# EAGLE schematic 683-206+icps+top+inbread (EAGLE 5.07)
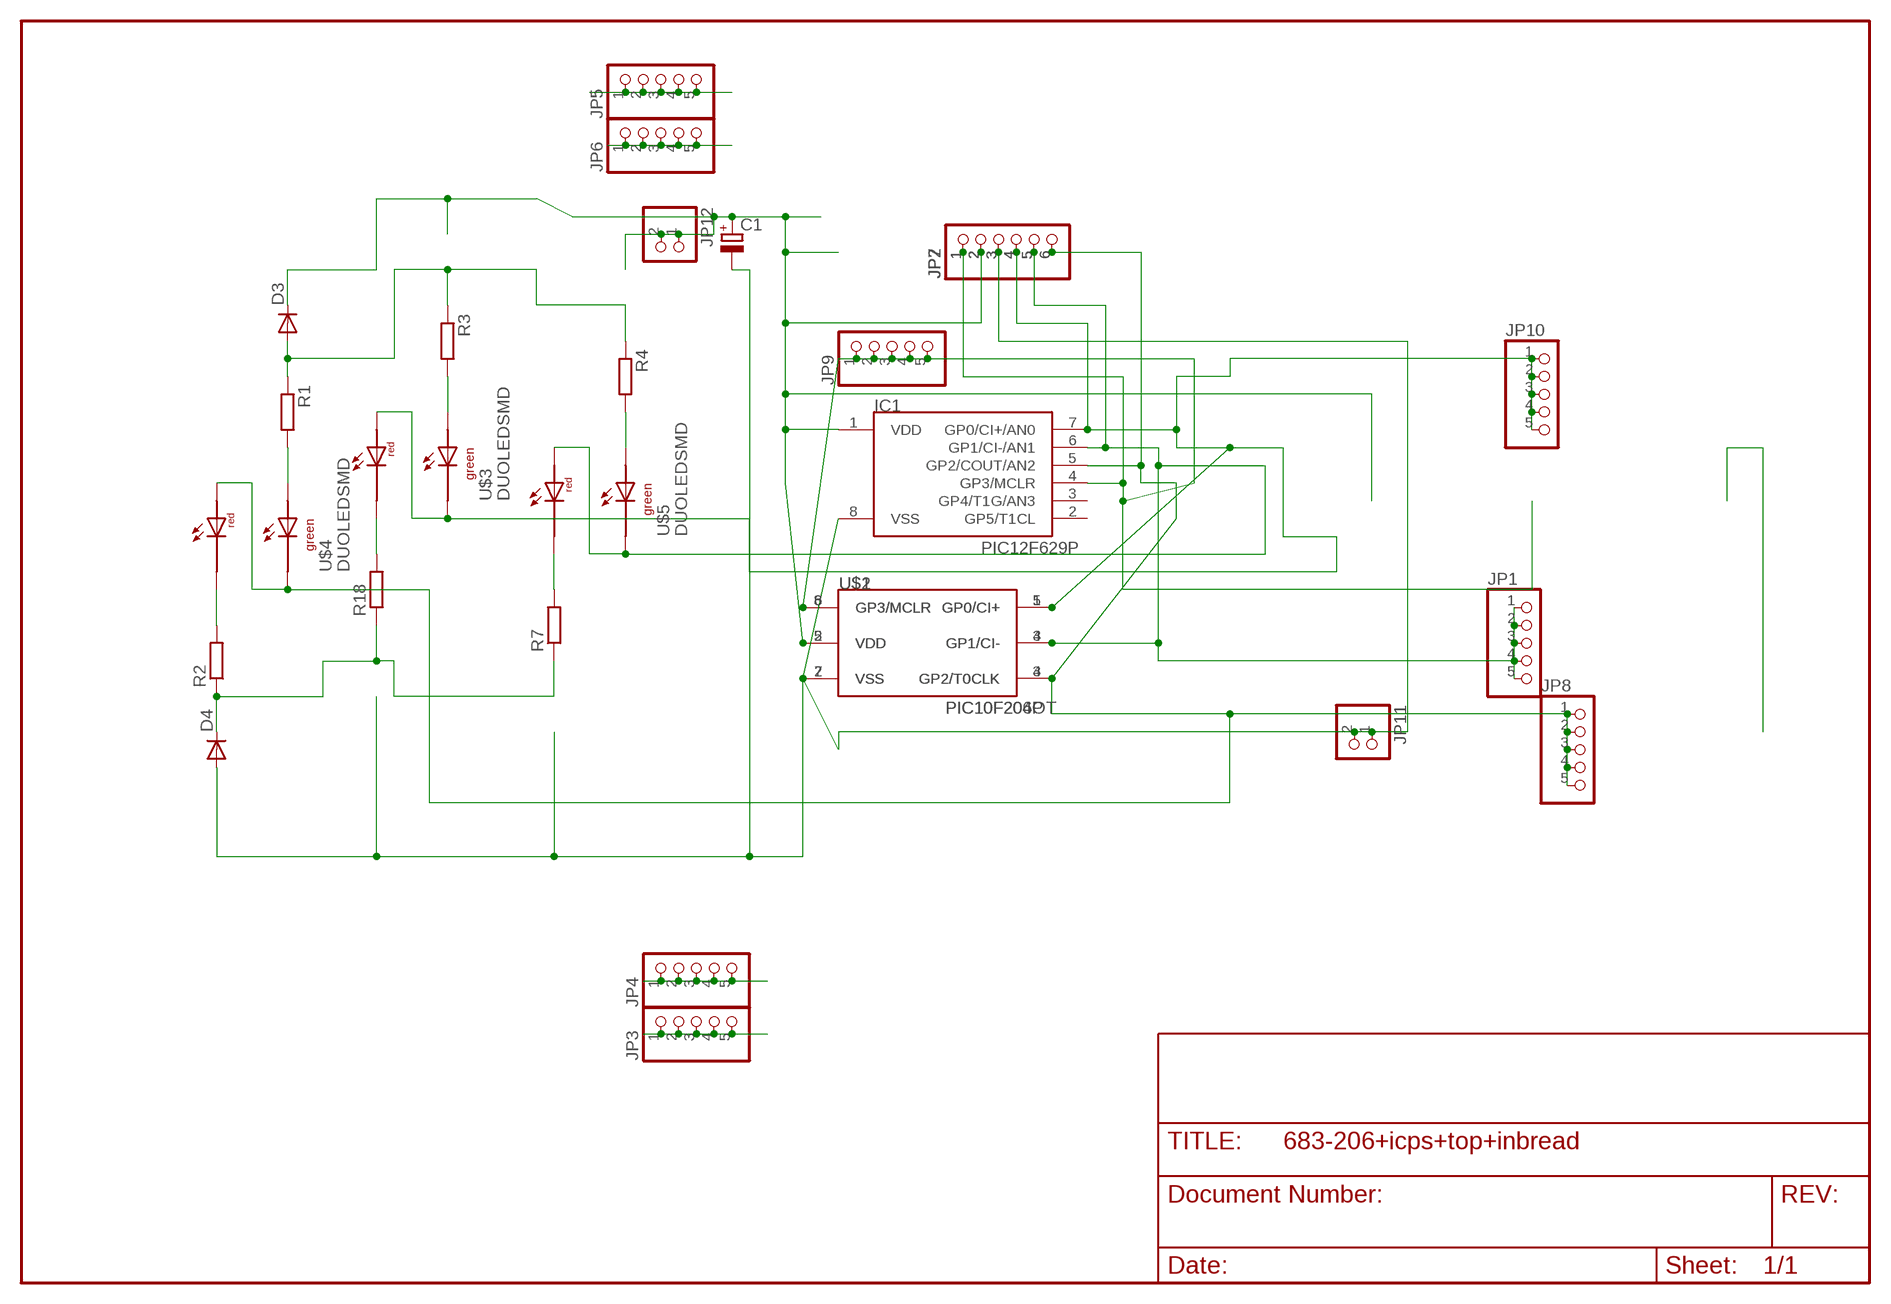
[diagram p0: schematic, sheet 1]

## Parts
C1  CPOL-EUE5-5  [E5-5]
D3  DIODE-MINIMELF  [MINIMELF]
D4  DIODE-MINIMELF  [MINIMELF]
IC1  PIC12F629P  [DIL8]
JP1  PINHD-1X5  [1X05]
JP2  PINHD-1X6  [1X06]
JP3  PINHD-1X5  [1X05]
JP4  PINHD-1X5  [1X05]
JP5  PINHD-1X5  [1X05]
JP6  PINHD-1X5  [1X05]
JP7  PINHD-1X6  [1X06]
JP8  PINHD-1X5  [1X05]
JP9  PINHD-1X5  [1X05]
JP10  PINHD-1X5  [1X05]
JP11  PINHD-1X2  [1X02]
JP12  PINHD-1X2  [1X02]
R1  R-EU_R1206  [R1206]
R2  R-EU_R1206  [R1206]
R3  R-EU_R1206  [R1206]
R4  R-EU_R1206  [R1206]
R7  R-EU_R1206  [R1206]
R18  R-EU_R1206  [R1206]
U$1  PIC10F206P  [DIL8]
U$2  PIC10F204OT  [SOT23-6]
U$3  DUOLEDSMD  [DUOLEDSMD]
U$4  DUOLEDSMD  [DUOLEDSMD]
U$5  DUOLEDSMD  [DUOLEDSMD]

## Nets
GP0: IC1.7(GP0/CI+/AN0) JP2.4 JP7.4 JP10.1 JP10.2 JP10.3 JP10.4 JP10.5 U$1.5(GP0/CI+) U$2.1(GP0/CI+) U$3.ARED U$3.CGRN
GP1: IC1.6(GP1/CI-/AN1) JP1.1 JP1.2 JP1.3 JP1.4 JP1.5 JP2.5 JP7.5 U$1.4(GP1/CI-) U$2.3(GP1/CI-) U$5.ARED U$5.CGRN
GP2: IC1.5(GP2/COUT/AN2) JP2.6 JP7.6 JP8.1 JP8.2 JP8.3 JP8.4 JP8.5 U$1.3(GP2/T0CLK) U$2.4(GP2/T0CLK) U$4.ARED U$4.CGRN
GP3: IC1.4(GP3/MCLR) JP2.1 JP7.1 JP9.1 JP9.2 JP9.3 JP9.4 JP9.5 U$1.8(GP3/MCLR) U$2.6(GP3/MCLR)
N$1: JP4.1 JP4.2 JP4.3 JP4.4 JP4.5
N$2: JP3.1 JP3.2 JP3.3 JP3.4 JP3.5
N$3: R3.2 U$3.AGRN
N$4: JP6.1 JP6.2 JP6.3 JP6.4 JP6.5
N$5: JP5.1 JP5.2 JP5.3 JP5.4 JP5.5
N$6: R18.2 U$3.CRED
N$7: D4.C R2.1 R7.1 R18.1
N$8: D3.A R1.1 R3.1 R4.1
N$20: R1.2 U$4.AGRN
N$23: R2.2 U$4.CRED
N$30: R4.2 U$5.AGRN
N$32: R7.2 U$5.CRED
VDD: C1.+ D3.C IC1.1(VDD) JP2.2 JP7.2 JP12.1 JP12.2 U$1.2(VDD) U$2.5(VDD)
VSS: C1.- D4.A IC1.8(VSS) JP2.3 JP7.3 JP11.1 JP11.2 U$1.7(VSS) U$2.2(VSS)
Unconnected: IC1.2(GP5/T1CL) IC1.3(GP4/T1G/AN3)

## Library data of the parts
C1 = rcl:CPOL-EU: POLARIZED CAPACITOR, European symbol
D3 D4 = diode:DIODE-: DIODE
IC1 = microchip-5:PIC12F6*: uPC nW 1k Program Flash memory 2x Timer Comparator 10b A/D converter/ 4xIN
JP1 JP3-JP6 JP8-JP10 = pinhead(2):PINHD-1X5: PIN HEADER
JP2 JP7 = pinhead:PINHD-1X6: PIN HEADER
JP11 JP12 = pinhead(2):PINHD-1X2: PIN HEADER
R1-R4 R7 R18 = rcl:R-EU_: RESISTOR, European symbol
U$1 U$2 = microchip-5:PIC10F2*: uPC nW 0,25/0,5k Program Flash memory Comparator
U$3-U$5 = led:DUOLEDSMD

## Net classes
0 default: width 0.3 mm, drill 0.6 mm, clearance 0.2 mm
1 power: width 0.4 mm, drill 0.6 mm, clearance 0.2 mm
